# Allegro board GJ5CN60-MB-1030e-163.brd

Outline 196.2 x 189.15 mm; copper layers: TOP, L2_GND1, L3_IN1, L4_VCC1, L5_VCC2, L6_IN2, L7_GND2, L8_IN3, L9_GND3, BOTTOM. Coordinates in mm from the lower left corner of the outline.

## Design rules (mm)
net group 0_CAP: nets CAP+ CAP-
net group 0_SPKL1: nets SPKL1+ SPKL1-
net group 0_SPKR1: nets SPKR1+ SPKR1-
net group 20: nets USB_PN9 USB_PP9
net group AUX_EDP_CH_N: nets AUX_EDP_CH_N EDP_AUXN
net group AUX_EDP_CH_P: nets AUX_EDP_CH_P EDP_AUXP
net group CLK_24MHZ: nets PCH_XATL24_IN PCH_XTAL24_OUT
net group CNV_WR_CLK: nets CNV_WR_CLKN CNV_WR_CLKP
net group CNV_WR_D0: nets CNV_WR_D0N CNV_WR_D0P
net group CNV_WR_D1: nets CNV_WR_D1N CNV_WR_D1P
net group DIFFPAIR529: nets JACK_HP_L JACK_HP_R
net group DIFFPAIR531: nets HP_L HP_R
net group DIFFPAIR545: nets GPU_NVVDDS_FBRTN GPU_NVVDDS_SENSE
net group DIFFPAIR552: nets I2CC_SCL_G I2CC_SDA_G
net group DIFFPAIR553: nets I2CC_SCL I2CC_SDA
net group DIFFPAIR566: nets PCIE10_TXN PCIE10_TXP
net group DIFFPAIR567: nets PCIE11_TXN PCIE11_TXP
net group DIFFPAIR569: nets PCIE9_RXN PCIE9_RXP
net group DIFFPAIR587: nets I2CB_SCL_G I2CB_SDA_G
net group DIFFPAIR649: nets LINE2_L LINE2_R
net group DIFFPAIR669: nets E-USB-N2 E-USB-P2
net group DIFFPAIR723: nets PCIE20_RXN PCIE20_RXP
net group DIFFPAIR724: nets PCIE18_RXN PCIE18_RXP
net group DIFFPAIR725: nets PCIE19_RXN PCIE19_RXP
net group DIFFPAIR726: nets PCIE17_RXN PCIE17_RXP
net group DIFFPAIR727: nets CLK_CPU_BCLK_DN CLK_CPU_BCLK_DP
net group DIFFPAIR728: nets CLK_CPU_24MHZ_DN CLK_CPU_24MHZ_DP
net group DIFFPAIR729: nets CLK_CPU_PCIBCLK_DN CLK_CPU_PCIBCLK_DP
net group DIFFPAIR736: nets CLK_PCIE_WLAN_DN CLK_PCIE_WLAN_DP
net group DIFFPAIR746: nets N27873712 N27873827
net group DP9: nets IFPE_AUX_CK IFPE_AUX_DATA
net group DP_D0+: nets DP_D0+ EDP_TXP0
net group DP_D0-: nets DP_D0- EDP_TXN0
net group DP_D1+: nets DP_D1+ EDP_TXP1
net group DP_D1-: nets DP_D1- EDP_TXN1
net group DP_D2+: nets DP_D2+ EDP_TXP2
net group DP_D2-: nets DP_D2- EDP_TXN2
net group DP_D3+: nets DP_D3+ EDP_TXP3
net group DP_D3-: nets DP_D3- EDP_TXN3
net group I_VIN_N: nets I_VIN_N VIN1N_INA
net group TEMP_MPS: nets TEMP_MPS VRA_VTEMP
net group UART: nets UART2_DEBUG_RXD UART2_DEBUG_TXD
net group USB_PN2: nets N27867078 USB_PN2
net group USB_PP2: nets N27867098 USB_PP2
net group VCORE_VSSSENSE: nets VCORE_VSSSENSE VRACPU_VORTN
net group VRACPU_VDIFF: nets VRACPU_VDIFF VRACPU_VFB
net group VRAGT_VORTN: nets VRAGT_VORTN VSSGT_SENSE
net group 50_OHM: nets PLT_RST# SMBCLK_EC SMBDAT_EC
net group 85_OHM: nets E-USB-N1 E-USB-P1 PCIE_DETECT_SSD1
net group AUDIO: nets ACZ_BITCLK ACZ_BITCLK_PCH ACZ_RST# ACZ_RST#_PCH ACZ_SDATAIN0 ACZ_SDATAOUT ACZ_SDOUT_PCH ACZ_SYNC ACZ_SYNC_PCH
net group BAT: nets ACZ_SPKR_B1 ACZ_SPKR_B2 BAT_SMBCLK BAT_SMBDAT
net group BT/WIFI: nets CNV_BRI_DT CNV_BRI_RSP CNV_RGI_DT CNV_RGI_RSP
net group CLK_SRC: nets CLK_EC_LPC CLK_LAN_REQ CLK_TPM GFX_CLKREQ LAN_XTAL_IN LAN_XTAL_OUT MINI_CLKREQ0# MODEM_CLKREQ
net group CLS_DDR4_A_D0: nets M_A_DQ0 M_A_DQ1 M_A_DQ2 M_A_DQ3 M_A_DQ4 M_A_DQ5 M_A_DQ6 M_A_DQ7 M_B_DQ0 M_B_DQ1 M_B_DQ2 M_B_DQ3 M_B_DQ4 M_B_DQ5 M_B_DQ6 M_B_DQ7
net group CLS_DDR4_A_D1: nets M_A_DQ8 M_A_DQ9 M_A_DQ10 M_A_DQ11 M_A_DQ12 M_A_DQ13 M_A_DQ14 M_A_DQ15 M_B_DQ8 M_B_DQ9 M_B_DQ10 M_B_DQ11 M_B_DQ12 M_B_DQ13 M_B_DQ14 M_B_DQ15
net group CLS_DDR4_A_D2: nets M_A_DQ16 M_A_DQ17 M_A_DQ18 M_A_DQ19 M_A_DQ20 M_A_DQ21 M_A_DQ22 M_A_DQ23 M_B_DQ16 M_B_DQ17 M_B_DQ18 M_B_DQ19 M_B_DQ20 M_B_DQ21 M_B_DQ22 M_B_DQ23
net group CLS_DDR4_A_D3: nets M_A_DQ24 M_A_DQ25 M_A_DQ26 M_A_DQ27 M_A_DQ28 M_A_DQ29 M_A_DQ30 M_A_DQ31 M_B_DQ24 M_B_DQ25 M_B_DQ26 M_B_DQ27 M_B_DQ28 M_B_DQ29 M_B_DQ30 M_B_DQ31
net group CLS_DDR4_A_D4: nets M_A_DQ32 M_A_DQ33 M_A_DQ34 M_A_DQ35 M_A_DQ36 M_A_DQ37 M_A_DQ38 M_A_DQ39 M_B_DQ32 M_B_DQ33 M_B_DQ34 M_B_DQ35 M_B_DQ36 M_B_DQ37 M_B_DQ38 M_B_DQ39
net group CLS_DDR4_A_D5: nets M_A_DQ40 M_A_DQ41 M_A_DQ42 M_A_DQ43 M_A_DQ44 M_A_DQ45 M_A_DQ46 M_A_DQ47 M_B_DQ40 M_B_DQ41 M_B_DQ42 M_B_DQ43 M_B_DQ44 M_B_DQ45 M_B_DQ46 M_B_DQ47
net group CLS_DDR4_A_D6: nets M_A_DQ48 M_A_DQ49 M_A_DQ50 M_A_DQ51 M_A_DQ52 M_A_DQ53 M_A_DQ54 M_A_DQ55 M_B_DQ48 M_B_DQ49 M_B_DQ50 M_B_DQ51 M_B_DQ52 M_B_DQ53 M_B_DQ54 M_B_DQ55
net group CLS_DDR4_A_D7: nets M_A_DQ56 M_A_DQ57 M_A_DQ58 M_A_DQ59 M_A_DQ60 M_A_DQ61 M_A_DQ62 M_A_DQ63 M_B_DQ56 M_B_DQ57 M_B_DQ58 M_B_DQ59 M_B_DQ60 M_B_DQ61 M_B_DQ62 M_B_DQ63
net group CLS_DMI: nets DMI_RXN0 DMI_RXN1 DMI_RXN2 DMI_RXN3 DMI_RXP0 DMI_RXP1 DMI_RXP2 DMI_RXP3 DMI_TXN0 DMI_TXN1 DMI_TXN2 DMI_TXN3 DMI_TXP0 DMI_TXP1 DMI_TXP2 DMI_TXP3
net group CLS_FB_A_CLK: nets FBA_CLK0_N FBA_CLK0_P FBA_CLK1_N FBA_CLK1_P
net group CLS_FB_A_CMD: nets FBA_CMD0 FBA_CMD1 FBA_CMD2 FBA_CMD3 FBA_CMD4 FBA_CMD5 FBA_CMD6 FBA_CMD7 FBA_CMD8 FBA_CMD9 FBA_CMD10 FBA_CMD11 FBA_CMD12 FBA_CMD13 FBA_CMD14 FBA_CMD15
net group CLS_FB_A_CMD1: nets FBA_CMD16 FBA_CMD17 FBA_CMD18 FBA_CMD19 FBA_CMD20 FBA_CMD21 FBA_CMD22 FBA_CMD23 FBA_CMD24 FBA_CMD25 FBA_CMD26 FBA_CMD27 FBA_CMD28 FBA_CMD29 FBA_CMD30 FBA_CMD31
net group CLS_FB_A_WCK: nets FBA_WCK01_N FBA_WCK01_P FBA_WCK23_N FBA_WCK23_P FBA_WCK45_N FBA_WCK45_P FBA_WCK67_N FBA_WCK67_P
net group CLS_FB_B_CLK: nets FBB_CLK0_N FBB_CLK0_P FBB_CLK1_N FBB_CLK1_P
net group CLS_FB_B_CMD: nets FBB_CMD0 FBB_CMD1 FBB_CMD2 FBB_CMD3 FBB_CMD4 FBB_CMD5 FBB_CMD6 FBB_CMD7 FBB_CMD8 FBB_CMD9 FBB_CMD10 FBB_CMD11 FBB_CMD12 FBB_CMD13 FBB_CMD14 FBB_CMD15
net group CLS_FB_B_CMD1: nets FBB_CMD16 FBB_CMD17 FBB_CMD18 FBB_CMD19 FBB_CMD20 FBB_CMD21 FBB_CMD22 FBB_CMD23 FBB_CMD24 FBB_CMD25 FBB_CMD26 FBB_CMD27 FBB_CMD28 FBB_CMD29 FBB_CMD30 FBB_CMD31
net group CLS_FB_B_WCK: nets FBB_WCK01_N FBB_WCK01_P FBB_WCK23_N FBB_WCK23_P FBB_WCK45_N FBB_WCK45_P FBB_WCK67_N FBB_WCK67_P
net group CLS_FB_C_CLK: nets FBC_CLK0_N FBC_CLK0_P FBC_CLK1_N FBC_CLK1_P
net group CLS_FB_C_CMD: nets FBC_CMD0 FBC_CMD1 FBC_CMD2 FBC_CMD3 FBC_CMD4 FBC_CMD5 FBC_CMD6 FBC_CMD7 FBC_CMD8 FBC_CMD9 FBC_CMD10 FBC_CMD11 FBC_CMD12 FBC_CMD13 FBC_CMD14 FBC_CMD15
net group CLS_FB_C_CMD1: nets FBC_CMD16 FBC_CMD17 FBC_CMD18 FBC_CMD19 FBC_CMD20 FBC_CMD21 FBC_CMD22 FBC_CMD23 FBC_CMD24 FBC_CMD25 FBC_CMD26 FBC_CMD27 FBC_CMD28 FBC_CMD29 FBC_CMD30 FBC_CMD31
net group CLS_FB_C_WCK: nets FBC_WCK01_N FBC_WCK01_P FBC_WCK23_N FBC_WCK23_P FBC_WCK45_N FBC_WCK45_P FBC_WCK67_N FBC_WCK67_P
net group CLS_LAN_TR: nets TR0+ TR0- TR1+ TR1- TR2+ TR2- TR3+ TR3-
net group CLS_LN_MDI: nets LAN_MDI0+ LAN_MDI0- LAN_MDI1+ LAN_MDI1- LAN_MDI2+ LAN_MDI2-
net group CLS_LPC: nets LPC_AD0 LPC_AD1 LPC_AD2 LPC_AD3 LPC_FRAME#
net group CLS_PCIE_CLK: nets CLK_PCIE_GFX_DN CLK_PCIE_GFX_DP CLK_PCIE_LAN_DN CLK_PCIE_LAN_DP PCIE4_CLKN_MD2_SSD1 PCIE4_CLKP_MD2_SSD1 PCIE6_CLKN_MD2_SSD2 PCIE6_CLKP_MD2_SSD2
net group CLS_PCIE_P: nets DGPU_PEX_RXN_0 DGPU_PEX_RXN_1 DGPU_PEX_RXN_2 DGPU_PEX_RXN_3 DGPU_PEX_RXN_4 DGPU_PEX_RXN_5 DGPU_PEX_RXN_6 DGPU_PEX_RXN_7 DGPU_PEX_RXN_8 DGPU_PEX_RXN_9 DGPU_PEX_RXN_10 DGPU_PEX_RXN_11 DGPU_PEX_RXN_12 DGPU_PEX_RXN_13 DGPU_PEX_RXN_14 DGPU_PEX_RXN_15 DGPU_PEX_RXP_0 DGPU_PEX_RXP_1 DGPU_PEX_RXP_2 DGPU_PEX_RXP_3 DGPU_PEX_RXP_4 DGPU_PEX_RXP_5 DGPU_PEX_RXP_6 DGPU_PEX_RXP_7 DGPU_PEX_RXP_8 DGPU_PEX_RXP_9 DGPU_PEX_RXP_10 DGPU_PEX_RXP_11 DGPU_PEX_RXP_12 DGPU_PEX_RXP_13 DGPU_PEX_RXP_14 DGPU_PEX_RXP_15 DGPU_PEX_TXN_0 DGPU_PEX_TXN_1 DGPU_PEX_TXN_2 DGPU_PEX_TXN_3 DGPU_PEX_TXN_4 DGPU_PEX_TXN_5 DGPU_PEX_TXN_6 DGPU_PEX_TXN_7 DGPU_PEX_TXN_8 DGPU_PEX_TXN_9 DGPU_PEX_TXN_10 DGPU_PEX_TXN_11 DGPU_PEX_TXN_12 DGPU_PEX_TXN_13 DGPU_PEX_TXN_14 DGPU_PEX_TXN_15 DGPU_PEX_TXP_1 DGPU_PEX_TXP_3 DGPU_PEX_TXP_5 DGPU_PEX_TXP_7 DGPU_PEX_TXP_9 DGPU_PEX_TXP_11 DGPU_PEX_TXP_13 DGPU_PEX_TXP_15 PEG_TXN0 PEG_TXN1 PEG_TXN2 PEG_TXN3 PEG_TXN4 PEG_TXN5 PEG_TXN6 PEG_TXN7 PEG_TXN8 PEG_TXN9 PEG_TXN10 PEG_TXN11 PEG_TXN12 PEG_TXN13 PEG_TXN14 PEG_TXN15 PEG_TXP0 PEG_TXP1 PEG_TXP2 PEG_TXP3 PEG_TXP4 PEG_TXP5 PEG_TXP6 PEG_TXP7 PEG_TXP8 PEG_TXP9 PEG_TXP10 PEG_TXP11 PEG_TXP12 PEG_TXP13 PEG_TXP14 PEG_TXP15 PEX_RXN0 PEX_RXN1 PEX_RXN2 PEX_RXN3 PEX_RXN4 PEX_RXN5 PEX_RXN6 PEX_RXN7 PEX_RXN8 PEX_RXN9 PEX_RXN10 PEX_RXN11 PEX_RXN12 PEX_RXN13 PEX_RXN14 PEX_RXN15 PEX_RXP0 PEX_RXP1 PEX_RXP2 PEX_RXP3 PEX_RXP4 PEX_RXP5 PEX_RXP6 PEX_RXP7 PEX_RXP8 PEX_RXP9 PEX_RXP10 PEX_RXP11 PEX_RXP12 PEX_RXP13 PEX_RXP14 PEX_RXP15
net group CLS_SATA: nets SATA_RXN0 SATA_RXN0_C SATA_RXP0 SATA_RXP0_C SATA_TXN0 SATA_TXN0_C SATA_TXP0 SATA_TXP0_C
net group CLS_USB3: nets USB3_TX1_N_C USB3_TX1_P_C USB3_TX3_N_C USB3_TX3_P_C USB3_TX5_N_C USB3_TX5_P_C USB3_TX6_N_C USB3_TX6_P_C USB31_5_RX_N USB31_5_RX_P USB31_5_TX_N USB31_5_TX_P USB31_6_RX_N USB31_6_RX_P USB31_6_TX_N USB31_6_TX_P USB32_RX_N_IN USB32_RX_P_IN USB32_TX_N_IN USB32_TX_P_IN USB33_RX_N_IN USB33_RX_P_IN USB33_TX_N_IN USB33_TX_P_IN
net group CNVIO: nets CNV_WT_CLKN CNV_WT_CLKP CNV_WT_D0N CNV_WT_D0P CNV_WT_D1N CNV_WT_D1P
net group DDR4_A_CMD: nets DDR0_A_ALERT_N DDR0_A_PARITY M_A_A0 M_A_A1 M_A_A2 M_A_A3 M_A_A4 M_A_A5 M_A_A6 M_A_A7 M_A_A8 M_A_A9 M_A_A10_AP M_A_A11 M_A_A12 M_A_A13 M_A_A14_MA_WE# M_A_A15_MA_CAS# M_A_A16_MA_RAS# M_A_ACT_N M_A_BA0 M_A_BA1 M_A_BG0 M_A_BG1
net group DDR4_A_CTRL: nets MA_CKE0 MA_CKE1 MA_CS#0 MA_CS#1 MA_ODT0 MA_ODT1
net group DDR4_B_CMD: nets DDR1_B_ALERT_N DDR1_B_PARITY M_B_A0 M_B_A1 M_B_A2 M_B_A3 M_B_A4 M_B_A5 M_B_A6 M_B_A7 M_B_A8 M_B_A9 M_B_A10_AP M_B_A11 M_B_A12 M_B_A13 M_B_A14_MB_WE# M_B_A15_MB_CAS# M_B_A16_MB_RAS# M_B_ACT_N M_B_BA0 M_B_BA1 M_B_BG0 M_B_BG1
net group DDR4_B_CTRL: nets MB_CKE0 MB_CKE1 MB_CS#0 MB_CS#1 MB_ODT0 MB_ODT1
net group DDR4_CLK: nets MA_CLK0 MA_CLK1 MA_CLK#0 MA_CLK#1 MB_CLK1 MB_CLK#1
net group DDR4_DQS: nets M_A_DQS3 M_A_DQS5 M_A_DQS#3 M_A_DQS#5 M_B_DQS0 M_B_DQS1 M_B_DQS2 M_B_DQS3 M_B_DQS4 M_B_DQS5 M_B_DQS6 M_B_DQS#0 M_B_DQS#1 M_B_DQS#2 M_B_DQS#3 M_B_DQS#4 M_B_DQS#5 M_B_DQS#6
net group DIFFPAIR570: nets PCIE9_TXN
net group FB_A_D0: nets FBA_D0 FBA_D1 FBA_D2 FBA_D3 FBA_D4 FBA_D5 FBA_D6 FBA_D7 FBA_DBI0 FBA_EDC0
net group FB_A_D1: nets FBA_D8 FBA_D9 FBA_D10 FBA_D11 FBA_D12 FBA_D13 FBA_D14 FBA_D15 FBA_DBI1 FBA_EDC1
net group FB_A_D2: nets FBA_D16 FBA_D17 FBA_D18 FBA_D19 FBA_D20 FBA_D21 FBA_D22 FBA_D23 FBA_DBI2 FBA_EDC2
net group FB_A_D3: nets FBA_D24 FBA_D25 FBA_D26 FBA_D27 FBA_D28 FBA_D29 FBA_D30 FBA_D31 FBA_DBI3 FBA_EDC3
net group FB_A_D4: nets FBA_D32 FBA_D33 FBA_D34 FBA_D35 FBA_D36 FBA_D37 FBA_D38 FBA_D39 FBA_DBI4 FBA_EDC4
net group FB_A_D5: nets FBA_D40 FBA_D41 FBA_D42 FBA_D43 FBA_D44 FBA_D45 FBA_D46 FBA_D47 FBA_DBI5 FBA_EDC5
net group FB_A_D6: nets FBA_D48 FBA_D49 FBA_D50 FBA_D51 FBA_D52 FBA_D53 FBA_D54 FBA_D55 FBA_DBI6 FBA_EDC6
net group FB_A_D7: nets FBA_D56 FBA_D57 FBA_D58 FBA_D59 FBA_D60 FBA_D61 FBA_D62 FBA_D63 FBA_DBI7 FBA_EDC7
net group FB_B_D_0: nets FBB_D0 FBB_D1 FBB_D2 FBB_D3 FBB_D4 FBB_D5 FBB_D6 FBB_D7 FBB_DBI0 FBB_EDC0
net group FB_B_D_1: nets FBB_D8 FBB_D9 FBB_D10 FBB_D11 FBB_D12 FBB_D13 FBB_D14 FBB_D15 FBB_DBI1 FBB_EDC1
net group FB_B_D_2: nets FBB_D16 FBB_D17 FBB_D18 FBB_D19 FBB_D20 FBB_D21 FBB_D22 FBB_D23 FBB_DBI2 FBB_EDC2
net group FB_B_D_3: nets FBB_D24 FBB_D25 FBB_D26 FBB_D27 FBB_D28 FBB_D29 FBB_D30 FBB_D31 FBB_DBI3 FBB_EDC3
net group FB_B_D_4: nets FBB_D32 FBB_D33 FBB_D34 FBB_D35 FBB_D36 FBB_D37 FBB_D38 FBB_D39 FBB_DBI4 FBB_EDC4
net group FB_B_D_5: nets FBB_D40 FBB_D41 FBB_D42 FBB_D43 FBB_D44 FBB_D45 FBB_D46 FBB_D47 FBB_DBI5 FBB_EDC5
net group FB_B_D_6: nets FBB_D48 FBB_D49 FBB_D50 FBB_D51 FBB_D52 FBB_D53 FBB_D54 FBB_D55 FBB_DBI6 FBB_EDC6
net group FB_B_D_7: nets FBB_D56 FBB_D57 FBB_D58 FBB_D59 FBB_D60 FBB_D61 FBB_D62 FBB_D63 FBB_DBI7 FBB_EDC7
net group FB_C_D_0: nets FBC_D0 FBC_D1 FBC_D2 FBC_D3 FBC_D4 FBC_D5 FBC_D6 FBC_D7 FBC_DBI0 FBC_EDC0
net group FB_C_D_1: nets FBC_D8 FBC_D9 FBC_D10 FBC_D11 FBC_D12 FBC_D13 FBC_D14 FBC_D15 FBC_DBI1 FBC_EDC1
net group FB_C_D_2: nets FBC_D16 FBC_D17 FBC_D18 FBC_D19 FBC_D20 FBC_D21 FBC_D22 FBC_D23 FBC_DBI2 FBC_EDC2
net group FB_C_D_3: nets FBC_D24 FBC_D25 FBC_D26 FBC_D27 FBC_D28 FBC_D29 FBC_D30 FBC_D31 FBC_DBI3 FBC_EDC3
net group FB_C_D_4: nets FBC_D32 FBC_D33 FBC_D34 FBC_D35 FBC_D36 FBC_D37 FBC_D38 FBC_D39 FBC_DBI4 FBC_EDC4
net group FB_C_D_5: nets FBC_D40 FBC_D41 FBC_D42 FBC_D43 FBC_D44 FBC_D45 FBC_D46 FBC_D47 FBC_DBI5 FBC_EDC5
net group FB_C_D_6: nets FBC_D48 FBC_D49 FBC_D50 FBC_D51 FBC_D52 FBC_D53 FBC_D54 FBC_D55 FBC_DBI6 FBC_EDC6
net group FB_C_D_7: nets FBC_D56 FBC_D57 FBC_D58 FBC_D59 FBC_D60 FBC_D61 FBC_D62 FBC_D63 FBC_DBI7 FBC_EDC7
net group HDMIOUT_CLK+: nets HDMI1_CLK_DP HDMIOUT_CLK+ N24336873 TMDSB_CLK+
net group HDMIOUT_CLK-: nets HDMI1_CLK_DN HDMIOUT_CLK- N24336854 TMDSB_CLK-
net group HDMIOUT_D0+: nets HDMI1_TX0_DP HDMIOUT_D0+ N24336578 TMDSB_D0+
net group HDMIOUT_D0-: nets HDMI1_TX0_DN HDMIOUT_D0- N24336526 TMDSB_D0-
net group HDMIOUT_D1+: nets HDMI1_TX1_DP HDMIOUT_D1+ N24336705 TMDSB_D1+
net group HDMIOUT_D1-: nets HDMI1_TX1_DN HDMIOUT_D1- N24336650 TMDSB_D1-
net group HDMIOUT_D2+: nets HDMI1_TX2_DP HDMIOUT_D2+ N24336771 TMDSB_D2+
net group HDMIOUT_D2-: nets HDMI1_TX2_DN HDMIOUT_D2- N24336752 TMDSB_D2-
net group PCH_SPI: nets PCH_SPI0_IO2 PCH_SPI0_IO3 PCH_SPI_CLK PCH_SPI_CS0# PCH_SPI_HOLD# PCH_SPI_SI PCH_SPI_SI_R PCH_SPI_SO PCH_SPI_SO_R PCH_SPI_WP PCH_XCLK_BIASREF
net group PCIE: nets N28935332 N28935334 PCIE9_TXN_C PCIE9_TXP PCIE9_TXP_C PCIE10_RXN PCIE10_RXP PCIE10_TXN_C PCIE10_TXP_C PCIE11_RXN PCIE11_RXP PCIE11_TXN_C PCIE11_TXP_C PCIE12_RXN PCIE12_RXP PCIE12_TXN PCIE12_TXN_C PCIE12_TXP PCIE12_TXP_C PCIE14_RXN PCIE14_RXP PCIE14_TXN PCIE14_TXP PCIE15_RXN PCIE15_RXP PCIE15_TXN PCIE15_TXP PCIE17_TXN PCIE17_TXN_C PCIE17_TXP PCIE17_TXP_C PCIE18_TXN PCIE18_TXN_C PCIE18_TXP PCIE18_TXP_C PCIE19_TXN PCIE19_TXN_C PCIE19_TXP PCIE19_TXP_C PCIE20_TXN PCIE20_TXN_C PCIE20_TXP PCIE20_TXP_C PCIE_TXN14_C PCIE_TXP14_C
net group PEX_RXP1: nets DGPU_PEX_TXP_14
net group PEX_RXP3: nets DGPU_PEX_TXP_12
net group PEX_RXP5: nets DGPU_PEX_TXP_10
net group PEX_RXP7: nets DGPU_PEX_TXP_8
net group PEX_RXP9: nets DGPU_PEX_TXP_6
net group PEX_RXP11: nets DGPU_PEX_TXP_4
net group PEX_RXP13: nets DGPU_PEX_TXP_2
net group PEX_RXP15: nets DGPU_PEX_TXP_0
net group RTC: nets RTC_X1 RTC_X2 RTCRST# SRTCRST#
net group SIDEHAND: nets CATERR# EC_PECI H_THERMTRIP_N PCH_2_CPU_TRIGGER PCH_PCIE_WAKE# PCH_PLTRST_PROC PCH_PM_SYNC PCH_PWROK PM_DOWN PM_DOWN_R PM_SYNC PROCHOT# PROCHOT#_R PROCHOT_# PROCPWRGD_CPU VCCST_PWRGD VCCST_PWRGD_R VCCST_PWRON_R VR_VIDALERT# VR_VIDSCK VR_VIDSOUT
net group SPI: nets SPI_CE# SPI_SI SPI_SO
net group USB2.0: nets TYPE_C_D1+ TYPE_C_D1- TYPE_C_D2+ TYPE_C_D2- USB_PN1 USB_PN3 USB_PN4 USB_PN5 USB_PN6 USB_PN7 USB_PN8 USB_PN12 USB_PN13 USB_PN14 USB_PP1 USB_PP3 USB_PP4 USB_PP5 USB_PP6 USB_PP7 USB_PP8 USB_PP12 USB_PP13 USB_PP14
net group USB3: nets TYPC_RX1+ TYPC_RX1- TYPC_RX2+ TYPC_RX2- TYPC_TX1+ TYPC_TX1- TYPC_TX2+ TYPC_TX2- USB31_1_RX_N USB31_1_RX_P USB31_1_TX_N USB31_1_TX_P USB31_3_RX_N USB31_3_RX_P USB31_3_TX_N USB31_3_TX_P
nets with their own width: min track width 0.114; nets EDP_HPD
nets with their own width: min track width 0.254; nets +3.3VA_RTC JACK_MIC1_R MIC1_VREF_L MIC1_VREF_R
nets with their own width: min track width 0.381; nets DC_IN DC_IN+ DC_IN_B GND POWER
nets with their own width: min track width 0.508; nets 1V8_AON 1V8_MAIN +0.6V_DDR +1.00V_CPU +1.0VA_PCH +1.00VS_CPU +1.2VS +2.5VS +3.3V +3.3VA +3.3VDVDD +3.3VS +5V +5V_3.3V_L +5V_AMP +5VA +5VS +V_DDR_VREFCA_CHB_DIMM +VCCCORE +VCCDSW_3P3 +VCCGT +VCCIO +VCCSA BAT+ CHG_LX CODEC_GND EC_3.3VA FAN_SPEED FAN_SPEED1 FBCAL_GND FBVDDQ_MEM GND_BQ24781S HDMI_5V_C HDMI_+5V M_VREF_CA_DIMM0 NVVDDS PEX_VDD PWR_B_LED_GND PWR_LED+ S_GND_R V_DDR_CA_VREF VIN VIN_LCD VIN_LCD_IN0 WEBCAM_+5V
nets with their own width: min track width 0.635; nets G_HDR1_R G_LDR1 G_LDR2 PHASE_GCORE1

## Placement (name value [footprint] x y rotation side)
AB1  -  [M-R0402]  21.67 56.85 180 bottom
AB2  -  [M-R0603]  32.08 55.71 0 top
AB3  -  [M-R0402]  22.3 62.18 90 bottom
AB4  -  [M-R0402]  20.67 65.13 0 top
AB5  -  [M-R0402]  13.54 55.58 0 top
AB6  -  [M-R0603]  28.52 55.2 0 top
AB8  -  [M-B0603]  67.51 48.09 270 bottom
AB9  -  [M-B0603]  68.91 48.09 270 bottom
AB11  -  [M-B0603]  70.31 48.09 270 bottom
AB12  -  [M-B0603]  71.7 48.09 270 bottom
AC3  -  [M-C0402]  20.27 55.32 180 top
AC4  -  [M-C0603]  26.36 54.44 270 top
AC5  -  [M-C0402]  22.3 54.18 270 top
AC6  -  [M-C0402]  15.65 63.32 270 top
AC7  -  [M-C0402]  14.63 63.32 270 top
AC8  -  [M-C0603]  23.44 54.05 270 top
AC9  -  [M-C0402]  25.17 54.08 270 top
ACN1  VALUE*  [CON_WB-4H125_11255W90-NP_JCTC]  78.73 39.74 180 bottom
AR5  -  [M-R0402]  26.38 64.85 90 top
AR6  -  [M-R0402]  22.02 64.85 90 top
AR8  -  [M-R0402]  14.63 60.52 90 top
AR9  -  [M-R0402]  15.65 60.52 90 top
AR11  -  [M-R0402]  16.2 57.23 0 top
AR12  -  [M-R0402]  16.2 58.25 0 top
AR13  -  [M-R0402]  17.86 59.01 0 top
AR14  -  [M-R0402]  18.24 60.15 0 top
AR17  -  [M-R0402]  25.22 64.85 90 top
AR18  -  [M-R0402]  15.14 61.92 180 top
AR25  -  [M-R0603]  17.73 55.32 180 top
B1  -  [M-R0603]  163.78 15.57 180 top
B2  -  [M-B0402]  147.4 28.65 180 top
B7  -  [M-B0603]  79.07 159.85 90 top
B10  -  [M-B0603]  59.26 159.97 0 top
B12  -  [M-B0603]  59.26 161.37 0 top
B13  VALUE*  [M-B0805]  39.06 168.35 270 top
B14  -  [FUSE-0805]  77.29 159.21 90 top
B15  -  [M-B0402]  71.7 156.8 180 bottom
B16  -  [M-B0402]  71.7 155.53 180 bottom
B19  -  [M-B0603]  60.53 174.58 270 top
B20  VALUE*  [M-B0805]  36.78 168.35 270 top
B25  -  [FUSE-0805]  81.36 157.69 0 top
B26  -  [M-R0805]  71.2 159.97 90 top
B27  -  [M-R0402]  80.72 77.04 180 top
B34  -  [M-R0402]  82.63 77.04 0 top
B36  VALUE*  [M-B0805]  27 40.21 180 top
B37  VALUE*  [M-B0805]  27 44.02 180 top
C2  -  [M-C0402]  189.31 135.84 90 top
C3  -  [M-C0603]  117.42 145.24 90 bottom
C4  -  [M-C0402]  176.48 162.13 270 top
C5  -  [M-C0603]  139.14 114.38 180 bottom
C6  -  [M-C0603]  144.47 114.38 180 bottom
C7  -  [M-C0603]  147.01 123.4 0 bottom
C8  -  [M-C0402]  15.7 154.13 180 bottom
C9  -  [M-C0603]  139.14 112.98 180 bottom
C10  -  [M-C0603]  133.93 117.55 180 bottom
C11  -  [M-C0603]  133.81 121.75 180 bottom
C13  -  [M-C0402]  182.7 165.31 270 top
C14  -  [M-C0402]  171.53 158.83 90 top
C15  -  [M-C0402]  175.59 162.13 270 top
C16  -  [M-C0402]  184.48 86.57 180 bottom
C17  -  [M-C0402]  184.48 85.68 180 bottom
C18  -  [M-C0402]  184.48 84.79 180 bottom
C19  -  [M-C0402]  184.48 83.9 180 bottom
C21  -  [M-C0402]  183.72 81.99 0 bottom
C22  -  [M-C0603]  133.81 123.14 180 bottom
C23  -  [M-C0603]  183.46 79.84 180 bottom
C24  -  [M-C0603]  139.14 122 180 bottom
C25  -  [M-C0603]  141.81 113.02 0 bottom
C26  -  [M-C0603]  128.55 137.57 180 top
C27  -  [M-C0603]  128.52 134.78 180 top
C28  -  [M-C0603]  147.22 141.38 0 bottom
C29  -  [M-C0603]  147.29 135.36 0 top
C30  -  [M-C0603]  147.29 136.76 0 top
C31  -  [M-C0603]  114.12 144.22 180 top
C32  -  [M-C0603]  147.29 138.15 0 top
C33  -  [M-C0603]  139.14 123.4 180 bottom
C34  -  [M-C0603]  128.55 136.17 180 top
C35  -  [M-C0603]  141.81 114.42 0 bottom
C36  -  [M-C0603]  136.47 122 0 bottom
C37  -  [M-C0603]  114.12 140.03 180 top
C38  -  [M-C0603]  114.12 141.43 180 top
C39  -  [M-C0603]  114.12 147.02 180 top
C40  -  [M-C0603]  133.93 116.16 180 bottom
C41  -  [M-C0603]  133.93 114.76 180 bottom
C42  -  [M-C0402]  131.01 131.52 270 bottom
C43  -  [M-C0603]  136.47 112.98 0 bottom
C44  -  [M-C0402]  146.51 111.59 0 bottom
C45  -  [M-C0402]  144.47 111.59 180 bottom
C46  -  [M-C0402]  143.2 5.79 270 top
C47  -  [M-C0402]  131.27 114 90 bottom
C48  -  [M-C0402]  133.93 111.59 0 bottom
C49  -  [M-C0402]  134.95 128.86 270 bottom
C50  -  [M-C0402]  134.95 131.4 270 bottom
C51  -  [M-C0603]  114.12 145.62 180 top
C52  -  [M-C0402]  139.7 131.78 0 bottom
C53  -  [M-C0402]  135.08 126.44 270 bottom
C54  -  [M-C0402]  141.3 128.1 90 bottom
C55  -  [M-C0603]  144.47 112.98 180 bottom
C56  -  [M-C0402]  141.02 125.38 270 bottom
C57  -  [M-C0402]  132.54 131.4 270 bottom
C58  -  [M-C0402]  141.55 129.64 0 bottom
C59  -  [M-C0402]  144.35 126.7 90 bottom
C60  -  [M-C0402]  145.64 126.98 0 bottom
C61  -  [M-C0402]  144.35 129.24 90 bottom
C62  -  [M-C0402]  132.16 114 90 bottom
C63  -  [M-C0402]  143.71 131.02 90 bottom
C64  -  [M-C0402]  138.89 126.83 270 bottom
C65  -  [M-C0402]  137.24 132.03 270 bottom
C66  -  [M-C0402]  132.54 128.98 270 bottom
C67  -  [M-C0603]  147.01 122 0 bottom
C68  -  [M-C0402]  182.32 17.05 0 top
C69  -  [M-C0402]  143.13 125.23 0 bottom
C70  -  [M-C0603]  144.47 123.4 180 bottom
C71  -  [M-C0603]  141.81 123.4 0 bottom
C72  -  [M-C0402]  132.03 80.78 0 bottom
C73  -  [M-C0402]  136.09 81.23 90 bottom
C74  -  [M-C0402]  154.38 65.74 90 bottom
C75  -  [M-C0402]  138.12 130.64 270 bottom
C76  -  [M-C0402]  139.27 65.48 90 bottom
C77  -  [M-C0603]  139.39 132.92 0 bottom
C78  -  [M-C0402]  137.49 65.48 270 bottom
C79  -  [M-C0603]  146.38 124.92 0 bottom
C80  -  [M-C0402]  132.54 124.79 270 bottom
C81  -  [M-C0603]  133.93 113.36 180 bottom
C82  -  [M-C0402]  178.76 17.05 0 top
C83  -  [M-C0402]  91.13 44.15 270 top
C84  -  [M-C0402]  175.98 14.47 0 top
C85  -  [M-C0402]  89.25 47.07 270 top
C86  -  [M-C0402]  103.07 160.1 180 top
C87  -  [M-C0402]  176.48 16.97 0 top
C88  -  [M-C0402]  91.52 46.36 270 top
C89  -  [M-C0402]  102.95 162.77 270 top
C90  -  [M-C0603]  114.12 142.83 180 top
C91  -  [M-C0603]  144.47 122 180 bottom
C92  -  [M-C0603]  141.81 122 0 bottom
C93  -  [M-C0402]  155.85 127.08 180 bottom
C94  -  [M-C0402]  151.15 128.48 180 bottom
C95  -  [M-C0603]  151.97 124.67 0 bottom
C96  -  [M-C0402]  153.87 124.79 270 bottom
C97  -  [M-C0603]  151.97 123.27 0 bottom
C98  -  [M-C0603]  136.47 123.4 0 bottom
C99  -  [M-C0603]  152.86 114.38 0 bottom
C100  -  [M-C0402]  153.24 131.14 0 bottom
C101  -  [M-C0402]  160.48 114.89 0 bottom
C102  -  [M-C0603]  155.52 115.01 180 bottom
C103  -  [M-C0603]  133.93 118.95 180 bottom
C104  -  [M-C0603]  155.52 117.81 180 bottom
C105  -  [M-C0402]  159.97 116.54 0 bottom
C106  -  [M-C0603]  155.52 120.6 180 bottom
C107  -  [M-C0402]  159.82 121.97 0 bottom
C108  -  [M-C0603]  133.93 120.35 180 bottom
C109  -  [M-C0402]  160.48 114 0 bottom
C110  -  [M-C0603]  155.52 116.41 180 bottom
C111  -  [M-C0603]  155.52 119.21 180 bottom
C112  -  [M-C0603]  155.52 122 180 bottom
C113  -  [M-C0402]  190.45 104.98 0 top
C114  -  [M-C0402]  158.06 114 270 bottom
C115  -  [M-C0402]  154.15 111.59 180 bottom
C116  -  [M-C0603]  155.52 123.4 180 bottom
C117  -  [M-C0603]  152.86 112.98 0 bottom
C118  -  [M-C0402]  152.63 115.52 0 bottom
C119  -  [M-C0402]  186.13 111.71 0 bottom
C120  -  [M-C0402]  188.6 112.2 90 top
C121  -  [M-C0603]  148.03 114.38 180 bottom
C122  -  [M-C0603]  159.21 132.67 270 bottom
C123  -  [M-C0603]  149.55 123.27 0 bottom
C125  -  [M-C0603]  156.16 132.54 270 bottom
C126  -  [M-C0402]  160.22 14.68 270 top
C127  -  [M-C0603]  148.03 112.98 180 bottom
C128  -  [M-C0402]  59 55.96 270 top
C129  -  [M-C0402]  59.89 55.96 270 top
C130  -  [M-C0402]  29.41 65.1 180 top
C131  -  [M-C0402]  31.7 62.44 0 top
C132  -  [M-C0603]  155.52 113.62 180 bottom
C133  -  [M-C0402]  158.19 125.17 0 bottom
C134  -  [M-C0402]  65.53 59.01 180 top
C135  -  [M-C0603]  140.16 81.49 90 bottom
C136  -  [M-C0402]  29.41 61.55 180 top
C137  -  [M-C0402]  29.46 62.44 180 top
C138  -  [M-C0402]  31.7 63.33 0 top
C139  -  [M-C0402]  28.02 62.94 270 top
C140  -  [M-C0402]  24.33 64.85 90 top
C141  -  [M-C0402]  22.91 64.85 90 top
C142  -  [M-C0402]  144.22 25.35 180 bottom
C143  -  [M-C0603]  20.27 54.18 0 top
C144  -  [M-C0603]  169.87 141.81 90 bottom
C145  -  [M-C0402]  190.47 102.75 0 top
C146  -  [M-C0603]  131.14 116.92 0 bottom
C147  -  [M-C0402]  144.22 18.62 180 bottom
C148  -  [M-C0603]  171.14 134.95 0 top
C149  -  [M-C0603]  136.47 105.74 270 bottom
C150  -  [M-C0402]  130.89 123.98 0 bottom
C151  -  [M-C0402]  2.36 105.11 0 top
C152  -  [M-C0603]  171.09 137.67 0 top
C153  -  [M-C0603]  119.71 133.43 180 bottom
C154  -  [M-C0402]  187.88 102.95 90 top
C155  -  [M-C0402]  185.88 141.18 90 top
C156  -  [M-C0402]  186.89 141.18 90 top
C157  -  [M-C0402]  187.91 141.18 90 top
C158  -  [M-C0402]  182.7 139.14 0 top
C159  -  [M-C0603]  189.81 106.76 270 top
C160  -  [M-C0603]  191.29 106.76 270 top
C161  -  [M-C0402]  18.62 61.67 90 top
C162  -  [M-C0402]  165.81 21.42 0 bottom
C163  -  [M-C0402]  17.86 61.67 90 top
C164  -  [M-C0402]  29.41 59.64 180 top
C165  -  [M-C0402]  176.73 143.72 90 top
C166  -  [M-C0402]  176.73 145.49 270 top
C167  -  [M-C0603]  134.06 105.74 270 bottom
C168  -  [M-C0402]  165.81 22.3 0 bottom
C169  -  [M-C0603]  176.88 102.72 270 top
C170  -  [M-C0603]  175.46 102.72 270 top
C171  -  [M-C0603]  179.15 104.65 0 top
C172  -  [M-C0402]  29.92 58.75 180 top
C173  -  [M-C0603]  115.01 134.19 180 top
C174  -  [M-C0402]  191.59 134.45 0 top
C175  -  [M-C0402]  165.81 23.19 0 bottom
C176  -  [M-C0603]  143.59 68.41 90 bottom
C177  -  [M-C0402]  154.63 11.26 270 bottom
C178  -  [M-C0402]  18.03 56.86 270 top
C179  -  [M-C0402]  18.92 56.86 90 top
C180  -  [M-C0402]  31.82 58.32 0 top
C181  -  [M-C0603]  186.77 111.84 180 top
C182  -  [M-C0402]  144.22 17.73 180 bottom
C183  -  [M-C0402]  18.29 63.05 180 top
C184  -  [M-C0603]  150.06 105.87 270 bottom
C185  -  [M-C0603]  189.25 109.55 90 top
C186  -  [M-C0603]  131.27 119.74 0 bottom
C187  -  [M-C0603]  153.24 68.53 90 bottom
C188  -  [M-C0603]  122.25 127.84 180 bottom
C189  -  [M-C0603]  146.51 105.74 270 bottom
C190  -  [M-C0603]  178.31 102.72 270 top
C191  -  [M-C0603]  142.19 110.94 90 bottom
C192  -  [M-C0603]  171.14 143.21 0 top
C193  -  [M-C0603]  190.73 109.55 90 top
C194  -  [M-C0402]  14.81 56.85 270 top
C195  -  [M-C0402]  14.81 58.63 90 top
C196  -  [M-C0603]  143.59 105.74 270 bottom
C197  -  [M-C0603]  141.81 173.69 0 top
C198  -  [M-C0402]  121.87 170.39 180 bottom
C199  -  [M-C0603]  18.06 64.19 0 top
C200  -  [M-C0603]  141.81 173.69 0 bottom
C201  -  [M-C0603]  141.81 175.09 0 bottom
C202  -  [M-C0603]  141.81 175.09 0 top
C203  -  [M-C0402]  158.57 112.09 270 bottom
C204  -  [M-C0603]  121.74 132.16 180 bottom
C205  -  [M-C0402]  142.06 27.26 180 top
C206  -  [M-C0603]  151.46 105.87 270 bottom
C207  -  [M-C0402]  157.68 112.09 270 bottom
C208  -  [M-C0603]  131.14 121.9 0 bottom
C209  -  [M-C0402]  130.38 126.32 270 bottom
C210  -  [M-C0603]  171.09 136.3 0 top
C211  -  [M-C0603]  171.12 141.79 0 top
C212  -  [M-C0603]  131.39 105.74 270 bottom
C213  -  [M-C0603]  121.74 130.76 180 bottom
C214  -  [M-C0402]  165.81 25.48 0 bottom
C215  -  [M-C0603]  148.67 105.87 270 bottom
C216  -  [M-C0402]  183.84 151.72 90 top
C217  -  [M-C0603]  138.89 105.74 270 bottom
C218  -  [M-C0603]  141.43 105.74 270 bottom
C219  -  [M-C0402]  130.89 124.89 0 bottom
C220  -  [M-C0603]  121.74 129.37 180 bottom
C221  -  [M-C0603]  133.43 30.31 180 top
C222  -  [M-C0603]  121.87 26.37 0 bottom
C223  -  [M-C0402]  126.95 45.93 0 bottom
C224  -  [M-C0402]  126.95 43.26 0 bottom
C225  -  [M-C0402]  76.83 39.83 270 top
C226  -  [M-C0402]  148.54 40.59 270 top
C227  -  [M-C0402]  149.3 28.65 0 top
C228  -  [M-C0402]  135.38 38.97 0 top
C229  -  [M-C0402]  127.02 41.53 0 bottom
C230  -  [M-C0402]  147.65 40.59 270 top
C231  -  [M-C0402]  65.53 63.33 180 top
C232  -  [M-C0402]  36.01 37.68 90 top
C233  -  [M-C0402]  133.04 40.08 0 top
C234  -  [M-C0402]  127.05 40.64 0 bottom
C235  -  [M-C0402]  127.05 39.75 0 bottom
C236  -  [M-C0402]  133.04 40.97 0 top
C237  -  [M-C0402]  126.95 44.15 0 bottom
C239  -  [M-C0402]  126.95 45.04 0 bottom
C240  -  [M-C0402]  78.1 39.83 270 top
C241  -  [M-C0402]  120.47 37.54 0 bottom
C242  -  [M-C0402]  120.47 36.66 0 bottom
C243  -  [M-C0402]  135.36 40.01 0 top
C244  -  [M-C0402]  36.02 35.9 270 top
C245  -  [M-C0402]  133.04 38.81 0 top
C246  -  [M-C0402]  98.5 54.31 0 top
C247  -  [M-C0402]  100.79 50.32 270 top
C248  -  [M-C0402]  100.79 52.1 90 top
C249  -  [M-C0402]  133.04 37.93 0 top
C250  -  [M-C0402]  127.02 42.42 0 bottom
C252  -  [M-C0402]  89.99 52.53 180 top
C253  -  [M-C0402]  174.7 21.8 180 top
C254  -  [M-C0402]  178.92 24.18 270 top
C255  -  [M-C0402]  114.12 5.92 0 top
C256  -  [M-C0402]  79.35 39.83 270 top
C257  -  [M-C0402]  19.51 147.65 270 bottom
C258  -  [M-C0402]  80.62 39.83 270 top
C259  -  [M-C0402]  175.72 23.7 180 top
C260  -  [M-C0402]  110.06 10.24 270 top
C261  -  [M-C0402]  109.55 37.54 270 bottom
C262  -  [M-C0402]  114.5 40.34 270 top
C263  -  [M-C0402]  89.99 53.42 180 top
C264  -  [M-C0402]  95.33 56.09 90 top
C265  -  [M-C0402]  92.4 47.2 270 top
C266  -  [M-C0402]  93.29 47.2 270 top
C267  -  [M-C0402]  96.16 47.2 270 top
C268  -  [M-C0402]  110.44 37.54 270 bottom
C269  -  [M-C0402]  115.39 40.34 270 top
C270  -  [M-C0402]  113.11 40.34 270 bottom
C271  -  [M-C0402]  111.33 37.54 270 bottom
C272  -  [M-C0402]  24.33 116.79 180 top
C273  -  [M-C0402]  14.05 118.7 0 top
C274  -  [M-C0402]  23.19 150.07 180 bottom
C275  -  [M-C0402]  112.22 40.34 270 bottom
C276  -  [M-C0402]  104.85 30.94 90 bottom
C277  -  [M-C0402]  105.36 29.47 0 bottom
C278  -  [M-C0402]  23.32 137.49 0 bottom
C279  -  [M-C0402]  190.7 158.58 270 top
C280  -  [M-C0402]  134.06 15.07 180 top
C281  -  [M-C0402]  134.06 16.46 180 top
C282  -  [M-C0402]  20.14 150.07 180 bottom
C283  -  [M-C0603]  110.69 15.7 90 bottom
C284  -  [M-C0402]  131.77 11.38 90 top
C285  -  [M-C0402]  128.35 11.38 90 top
C286  -  [M-C0402]  190.85 97.89 90 top
C287  -  [M-C0402]  124.66 47.2 0 bottom
C288  -  [M-C0402]  182.7 141.81 0 top
C289  -  [M-C0402]  179.27 141.81 90 top
C290  -  [M-C0402]  95.83 25.23 0 top
C291  -  [M-C0402]  106.12 6.18 90 bottom
C292  -  [M-C0402]  169.11 8.59 90 top
C293  -  [M-C0402]  15.06 142.83 90 bottom
C294  -  [M-C0402]  156.03 8.72 0 top
C295  -  [M-C0402]  92.58 57.61 90 top
C296  -  [M-C0402]  168.22 8.59 90 top
C297  -  [M-C0402]  153.36 14.3 90 top
C298  -  [M-C0402]  154.63 14.3 90 top
C299  -  [M-C0402]  109.04 10.24 90 bottom
C300  -  [M-C0402]  124.66 48.09 0 bottom
C305  -  [M-C0402]  161.62 150.45 180 bottom
C308  -  [M-C0402]  193.8 95.33 0 top
C309  -  [M-C0402]  48.59 69.29 90 top
C310  -  [M-C0402]  193.83 93.42 0 top
C311  -  [M-C0402]  59.56 62.31 90 top
C320  -  [M-C0402]  132.66 11.38 90 top
C321  -  [M-C0402]  100.28 41.1 270 top
C322  -  [M-C0402]  132.66 36.4 90 top
C323  -  [M-C0402]  115.65 21.16 0 bottom
C324  -  [M-C0402]  130.5 11.89 0 top
C325  -  [M-C0402]  124.15 26.24 180 bottom
C326  -  [M-C0402]  109.17 16.72 90 bottom
C327  -  [M-C0402]  123.52 28.15 180 bottom
C328  -  [M-C0402]  110.44 20.91 270 bottom
C329  -  [M-C0402]  121.36 28.15 180 bottom
C330  -  [M-C0402]  89.99 64.47 90 top
C331  -  [M-C0402]  117.17 26.37 90 bottom
C332  -  [M-C0402]  97.23 47.2 270 top
C333  -  [M-C0402]  83.64 65.48 90 top
C334  -  [M-C0402]  145.52 52.45 0 bottom
C335  -  [M-C0402]  151.18 51.03 180 bottom
C339  -  [M-C0402]  129.23 11.38 90 top
C340  -  [M-C0603]  117.42 24.44 0 bottom
C341  -  [M-C0402]  113.11 16.72 0 bottom
C345  -  [M-C0402]  63.7 156.29 90 bottom
C346  -  [M-C0402]  64.59 156.29 90 bottom
C347  -  [M-C0402]  144.22 16.34 180 bottom
C349  -  [M-C0402]  61.04 156.29 270 bottom
C351  -  [M-C0402]  60.15 156.29 270 bottom
C352  -  [M-C0402]  62.81 156.29 270 bottom
C353  -  [M-C0402]  52.4 53.55 0 top
C354  -  [M-C0402]  61.92 156.29 270 bottom
C355  -  [M-C0402]  52.4 55.45 180 top
C359  -  [M-C0402]  98.6 52.4 0 top
C360  -  [M-C0402]  59.26 156.29 270 bottom
C361  -  [M-C0402]  58.37 156.29 270 bottom
C362  -  [M-C0402]  56.59 156.29 270 bottom
C363  -  [M-C0402]  57.48 156.29 270 bottom
C364  -  [M-C0402]  137.24 128.86 270 bottom
C365  -  [M-C0402]  63.51 167.97 90 top
C366  -  [M-C0402]  132.54 126.57 90 bottom
C367  -  [M-C0402]  137.24 126.57 90 bottom
C368  -  [M-C0402]  142.57 127.84 90 bottom
C369  -  [M-C0402]  67.07 167.97 90 top
C370  -  [M-C0402]  145.64 129.11 0 bottom
C371  -  [M-C0402]  130.38 114 90 bottom
C372  -  [M-C0402]  149.68 125.17 0 bottom
C373  -  [M-C0402]  150.44 91.77 90 top
C374  -  [M-C0402]  112.34 88.73 90 bottom
C375  -  [M-C0402]  148.72 127.77 180 bottom
C376  -  [M-C0402]  157.22 129.75 180 bottom
C377  -  [M-C0402]  155.4 125.3 270 bottom
C378  -  [M-C0402]  132.03 107.9 90 bottom
C379  -  [M-C0603]  87.58 56.85 90 top
C380  -  [M-C0402]  147.65 91.77 90 top
C381  -  [M-C0402]  143.84 110.32 180 bottom
C382  -  [M-C0402]  165.61 133.53 270 bottom
C383  -  [M-C0402]  166.5 133.53 270 bottom
C384  -  [M-C0402]  113.23 88.73 90 bottom
C385  -  [M-C0402]  116.03 80.98 270 bottom
C386  -  [M-C0402]  116.92 80.98 270 bottom
C387  -  [M-C0402]  171.91 76.41 90 bottom
C388  -  [M-C0402]  142.19 77.17 0 bottom
C389  -  [M-C0402]  113.49 75.9 180 bottom
C390  -  [M-C0402]  113.49 75.01 180 bottom
C391  -  [M-C0402]  116.66 67.9 270 bottom
C392  -  [M-C0402]  115.77 67.9 270 bottom
C393  -  [M-C0402]  65.84 161.37 0 top
C394  -  [M-C0402]  65.86 160.48 0 top
C395  -  [M-C0402]  144.47 124.92 270 bottom
C396  -  [M-C0402]  144.98 131.02 90 bottom
C397  -  [M-C0402]  130.89 128.6 270 bottom
C398  -  [M-C0402]  139.14 128.35 0 bottom
C399  -  [M-C0402]  150.44 132.16 180 bottom
C400  -  [M-C0402]  87.73 95.59 180 bottom
C401  -  [M-C0402]  150.57 141.07 180 bottom
C402  -  [M-C0603]  61.34 59.39 0 top
C403  -  [M-C0402]  66.18 167.97 90 top
C404  -  [M-C0402]  64.4 167.97 90 top
C405  -  [M-C0402]  87.71 94.57 180 bottom
C406  -  [M-C0402]  82.87 89.14 90 bottom
C407  -  [M-C0402]  44.02 62.06 270 bottom
C408  -  [M-C0402]  71.13 167.97 90 top
C409  -  [M-C0402]  72.02 167.97 90 top
C410  -  [M-C0402]  45.92 158.45 0 bottom
C411  -  [M-C0402]  68.59 167.97 90 top
C412  -  [M-C0402]  76.91 49.1 180 top
C413  -  [M-C0402]  79.83 46.56 90 top
C414  -  [M-C0402]  69.48 167.97 90 top
C415  -  [M-C0402]  81.98 89.14 90 bottom
C416  -  [M-C0402]  54.05 70.31 270 bottom
C417  -  [M-C0402]  41.73 134.45 0 top
C418  -  [M-C0402]  100.1 128.53 180 top
C419  -  [M-C0402]  53.03 157.43 90 top
C420  -  [M-C0402]  40.84 69.8 0 bottom
C421  -  [M-C0402]  80.09 93.04 180 bottom
C422  -  [M-C0402]  68.66 90.38 0 bottom
C423  -  [M-C0402]  61.92 142.07 90 bottom
C424  -  [M-C0402]  62.43 149.69 90 bottom
C425  -  [M-C0402]  69.42 75.14 270 bottom
C426  -  [M-C0402]  41.86 162.92 180 bottom
C427  -  [M-C0402]  82.12 133.18 270 top
C428  -  [M-C0402]  60.27 163.4 180 top
C429  -  [M-C0402]  97.61 140.03 270 top
C430  -  [M-C0402]  97.36 142.57 90 top
C431  -  [M-C0402]  61.16 169.5 0 top
C432  -  [M-C0402]  56.97 158.7 0 top
C433  -  [M-C0402]  97.36 144.35 90 top
C435  -  [M-C0402]  57.1 169.37 180 top
C436  -  [M-C0402]  181.56 159.08 90 top
C438  -  [M-C0402]  179.4 145.49 90 top
C445  -  [M-C0402]  28.02 162.89 90 top
C450  -  [M-C0402]  114.88 165.56 180 bottom
C452  -  [M-C0402]  74.24 161.88 0 top
C456  -  [M-C0402]  20.14 46.18 0 top
C465  -  [M-C0402]  67.89 156.8 180 bottom
C466  -  [M-C0402]  65.99 156.8 180 bottom
C469  -  [M-C0402]  40.84 167.59 90 top
C470  -  [M-C0402]  41.73 167.59 90 top
C473  -  [M-C0402]  77.16 163.02 270 top
C486  -  [M-C0402]  183.72 80.98 180 bottom
C492  -  [M-C0402]  150.44 9.22 270 top
C493  -  [M-C0402]  151.59 9.22 270 top
C498  -  [M-C0402]  108.66 37.54 270 bottom
C499  -  [M-C0402]  126.82 173.56 0 top
C500  -  [M-C0402]  129.36 173.05 0 bottom
C522  -  [M-C0402]  83.26 73.23 180 top
C529  -  [M-C0402]  89.2 160.35 270 top
C540  -  [M-C0402]  13.59 82.93 180 top
C544  -  [M-C0402]  16.33 72.72 0 bottom
C545  -  [M-C0402]  59.51 162.51 180 top
C546  -  [M-C0402]  11.56 74.37 270 top
C548  -  [M-C0402]  12.14 70.56 90 bottom
C550  -  [M-C0402]  22.68 106.89 270 top
C553  -  [M-C0603]  181.08 78.44 90 bottom
C554  -  [M-C0402]  10.74 83.21 180 top
C556  -  [M-C0402]  4.77 106.51 180 top
C559  -  [M-C0402]  2.36 106 0 top
C576  -  [M-C0805]  124.28 170.89 270 bottom
C577  -  [M-C0603]  146.63 131.4 0 bottom
C578  -  [M-C0603]  41.48 169.37 0 top
C579  -  [M-C0603]  136.47 114.38 0 bottom
C580  -  [M-C0603]  126.31 140.92 270 top
C581  -  [M-C0402]  182.22 104.27 90 top
C582  -  [M-C0603]  128.55 138.97 180 top
C583  -  [M-C0603]  127.71 140.92 270 top
C584  -  [M-C0603]  125.68 145.24 90 bottom
C585  -  [M-C0603]  150.32 133.3 180 bottom
C586  -  [M-C0603]  164.54 126.57 0 bottom
C587  -  [M-C0603]  140.03 145.24 90 bottom
C588  -  [M-C0402]  188.29 152.1 180 top
C589  -  [M-C0603]  137.24 145.24 90 bottom
C590  -  [M-C0603]  134.57 124.79 180 bottom
C591  -  [M-C0603]  144.22 145.24 90 bottom
C592  -  [M-C0402]  181.81 153.11 0 top
C593  -  [M-C0603]  128.85 145.24 90 bottom
C594  -  [M-C0603]  127.46 145.24 90 bottom
C595  -  [M-C0402]  43.51 167.59 270 top
C596  -  [M-C0603]  44.78 167.47 90 top
C597  -  [M-C0603]  41.48 170.77 0 top
C598  -  [M-C0603]  164.54 130.89 0 bottom
C599  -  [M-C0603]  171.12 140.41 0 top
C600  -  [M-C0603]  171.12 139.04 0 top
C601  -  [M-C0603]  162.89 141.81 90 bottom
C602  -  [M-C0402]  189.56 149.81 270 top
C603  -  [M-C0603]  121.49 145.24 90 bottom
C604  -  [M-C0603]  122.88 145.24 90 bottom
C605  -  [M-C0603]  120.09 145.24 90 bottom
C606  -  [M-C0603]  164.54 128.1 0 bottom
C607  -  [M-C0603]  134.44 145.24 90 bottom
C608  -  [M-C0603]  135.84 145.24 90 bottom
C609  -  [M-C0603]  142.82 145.24 90 bottom
C610  -  [M-C0402]  61.29 176.36 0 top
C611  -  [M-C0603]  147.01 145.24 90 bottom
C612  -  [M-C0603]  118.82 145.24 90 bottom
C613  -  [M-C0603]  148.41 145.24 90 bottom
C614  -  [M-C0603]  141.43 145.24 90 bottom
C615  -  [M-C0402]  182.32 151.72 270 top
C616  -  [M-C0603]  138.63 145.24 90 bottom
C617  -  [M-C0603]  130.25 145.24 90 bottom
C618  -  [M-C0603]  145.62 145.24 90 bottom
C619  -  [M-C0603]  131.65 145.24 90 bottom
C620  -  [M-C0603]  133.04 145.24 90 bottom
C621  -  [M-C0603]  162.64 132.29 0 bottom
C622  -  [M-C0603]  164.54 129.49 0 bottom
C623  -  [M-C0603]  162.64 133.68 0 bottom
C624  -  [M-C0603]  124.28 145.24 90 bottom
C625  -  [M-C0603]  168.48 141.84 90 bottom
C626  -  [M-C0603]  164.29 141.81 90 bottom
C627  -  [M-C0603]  167.08 141.81 90 bottom
C628  -  [M-C0603]  165.68 141.81 90 bottom
C629  -  [M-C1808]  78.17 174.59 180 top
C630  -  [M-C0805]  126.31 170.89 270 bottom
C631  -  [M-C0805]  121.87 172.8 180 top
C632  -  [M-C0805]  125.81 172.16 0 top
C641  -  [M-C0402]  184.48 162.89 90 top
C653  -  [M-C0402]  186.26 162.89 90 top
C654  -  [M-C0402]  192.61 144.35 0 top
C656  -  [M-C0402]  190.07 144.35 0 top
C663  -  [M-C0402]  9.09 98.76 270 top
C665  -  [M-C0402]  10.62 99.9 180 top
C666  -  [M-C0402]  6.96 106.63 180 top
C667  -  [M-C0402]  78.94 157.31 270 bottom
C668  -  [M-C0402]  8.46 106.89 90 top
C669  -  [M-C0402]  79.07 157.43 270 top
C673  -  [M-C0402]  4.77 104.22 270 top
C674  -  [M-C7343]  26.11 86.11 270 top
C675  -  [M-C7343]  145.74 141.05 0 top
C677  -  [M-C0603]  92.33 88.06 270 bottom
C686  -  [M-C0603]  22.94 89.74 180 bottom
C687  -  [M-C0603]  51.13 81.11 90 bottom
C688  -  [M-C0603]  68.27 88.6 45 bottom
C689  -  [M-C0603]  22.94 88.34 180 bottom
C690  -  [M-C0603]  22.94 79.45 180 bottom
C692  -  [M-C0603]  41.86 141.05 0 bottom
C693  -  [M-C0603]  41.86 143.08 0 top
C694  -  [M-C0603]  41.86 146.64 0 top
C695  -  [M-C0603]  41.86 144.99 0 top
C696  -  [M-C0603]  41.86 141.43 0 top
C697  -  [M-C0603]  41.86 133.56 0 bottom
C698  -  [M-C0603]  41.86 139.4 0 bottom
C699  -  [M-C0603]  41.86 149.18 0 bottom
C700  -  [M-C0603]  41.86 145.49 0 bottom
C701  -  [M-C0603]  41.86 148.16 0 top
C702  -  [M-C0603]  41.86 135.59 0 top
C703  -  [M-C0603]  41.86 137.75 0 top
C719  -  [M-C0603]  93.72 88.06 270 bottom
C720  -  [M-C0402]  21.41 74.25 270 bottom
C738  -  [M-C0402]  173.81 162.77 270 top
C782  -  [M-C0402]  87.81 103.19 0 bottom
C783  -  [M-C0402]  90.11 102.87 180 bottom
C784  -  [M-C0402]  87.81 104.07 0 bottom
C785  -  [M-C0402]  89.75 104.81 180 bottom
C788  -  [M-C0402]  108.03 115.52 180 bottom
C789  -  [M-C0402]  108.03 110.95 180 bottom
C796  -  [M-C0402]  22.1 65.89 0 bottom
C797  -  [M-C0402]  13.92 110.82 0 top
C798  -  [M-C0402]  24.64 66.73 270 bottom
C799  -  [M-C0402]  16.08 112.22 270 top
C800  -  [M-C0402]  14.3 114.63 180 top
C801  -  [M-C0402]  14.17 72.6 180 top
C802  -  [M-C0402]  15.57 72.22 90 top
C803  -  [M-C0402]  18.01 111.08 90 top
C804  -  [M-C0402]  25.35 131.14 0 top
C805  -  [M-C0402]  23.32 132.03 0 top
C806  -  [M-C0402]  25.35 146.51 0 top
C807  -  [M-C0402]  23.44 147.4 0 top
C808  -  [M-C0402]  25.22 158.58 0 top
C809  -  [M-C0402]  25.22 159.46 180 top
C816  -  [M-C0603]  17.47 66.25 180 bottom
C817  -  [M-C0603]  18.62 74.5 90 bottom
C818  -  [M-C0402]  24.15 70.92 0 bottom
C819  -  [M-C0402]  68.78 92.41 180 bottom
C821  -  [M-C0402]  105.99 114.38 180 bottom
C822  -  [M-C0402]  108.03 116.41 180 bottom
C823  -  [M-C0402]  108.03 113.24 180 bottom
C824  -  [M-C0402]  105.99 115.27 180 bottom
C825  -  [M-C0402]  105.99 112.09 180 bottom
C826  -  [M-C0402]  108.03 114.13 180 bottom
C827  -  [M-C0402]  105.99 109.81 180 bottom
C828  -  [M-C0402]  105.99 112.98 180 bottom
C829  -  [M-C0402]  108.03 111.84 180 bottom
C830  -  [M-C0402]  108.03 108.66 180 bottom
C831  -  [M-C0402]  105.99 110.7 180 bottom
C832  -  [M-C0402]  105.99 107.52 180 bottom
C833  -  [M-C0402]  108.03 109.55 180 bottom
C834  -  [M-C0402]  105.99 108.41 180 bottom
C846  -  [M-C0402]  105.99 105.11 180 bottom
C847  -  [M-C0402]  107.9 107.27 180 bottom
C848  -  [M-C0402]  107.9 106.38 180 bottom
C849  -  [M-C0402]  82.78 108.54 0 bottom
C851  -  [M-C0402]  105.99 106 180 bottom
C852  -  [M-C0402]  105.99 102.82 180 bottom
C853  -  [M-C0402]  108.03 104.85 180 bottom
C854  -  [M-C0402]  108.03 103.97 180 bottom
C855  -  [M-C0402]  105.99 103.71 180 bottom
C856  -  [M-C0603]  97.36 92.92 0 bottom
C857  -  [M-C0402]  85.07 88.7 180 bottom
C858  -  [M-C0402]  83.76 89.14 270 bottom
C859  -  [M-C0402]  105.99 100.54 180 bottom
C860  -  [M-C0603]  97.27 94.3 0 bottom
C861  -  [M-C0603]  84.61 86.16 270 bottom
C862  -  [M-C0603]  82.5 86.01 270 bottom
C863  -  [M-C0402]  87.83 98.5 0 bottom
C864  -  [M-C0402]  87.83 100.66 0 bottom
C865  -  [M-C0603]  81.61 65.87 0 top
C866  -  [M-C0603]  97.22 95.59 0 bottom
C867  -  [M-C0402]  108.03 102.57 180 bottom
C868  -  [M-C0402]  107.99 101.69 180 bottom
C870  -  [M-C0402]  87.83 101.81 0 bottom
C871  -  [M-C0603]  78.56 77.04 180 top
C872  -  [M-C0402]  108.15 63.71 90 top
C874  -  [M-C0402]  81.1 140.16 270 top
C875  -  [M-C0402]  79.2 137.87 0 bottom
C876  -  [M-C0402]  81.48 138.13 180 bottom
C877  -  [M-C0402]  38.94 122.13 90 bottom
C878  -  [M-C0402]  46.3 138 180 bottom
C879  -  [M-C0402]  39.11 87.18 90 bottom
C880  -  [M-C0402]  81.99 140.16 270 top
C881  -  [M-C0402]  72.72 89.13 270 bottom
C882  -  [M-C0402]  68.82 106.64 180 bottom
C883  -  [M-C0402]  68.78 99.65 180 bottom
C884  -  [M-C0402]  35.51 121.36 0 top
C885  -  [M-C0402]  69.04 133.68 270 bottom
C886  -  [M-C0402]  72.34 133.68 270 bottom
C887  -  [M-C0402]  63.19 142.57 90 top
C888  -  [M-C0402]  63.19 140.8 270 top
C889  -  [M-C0603]  74.24 148.29 0 top
C890  -  [M-C0402]  77.16 132.67 90 bottom
C891  -  [M-C0603]  68.53 148.16 0 top
C892  -  [M-C0603]  65.1 148.16 0 top
C893  -  [M-C0402]  63.58 133.56 270 bottom
C894  -  [M-C0603]  68.15 146.89 180 bottom
C895  -  [M-C0402]  63.83 138 90 bottom
C896  -  [M-C0603]  65.86 147.65 270 bottom
C897  -  [M-C0603]  75.01 148.54 0 bottom
C898  -  [M-C0402]  82.75 132.92 270 bottom
C899  -  [M-C0603]  84.66 148.29 180 bottom
C900  -  [M-C0603]  89.23 148.29 180 top
C901  -  [M-C0402]  91.9 134.83 0 bottom
C902  -  [M-C0603]  89.23 148.29 0 bottom
C903  -  [M-C0603]  94.31 148.29 0 top
C904  -  [M-C0402]  96.34 136.22 90 bottom
C905  -  [M-C0402]  82.63 140.92 90 bottom
C906  -  [M-C0402]  82.63 143.08 270 bottom
C907  -  [M-C0402]  82.63 146 90 bottom
C908  -  [M-C0402]  96.6 140.29 180 bottom
C909  -  [M-C0603]  95.45 147.91 0 bottom
C910  -  [M-C0603]  81.86 144.35 90 top
C911  -  [M-C0402]  43.26 112.35 0 bottom
C912  -  [M-C0402]  43.89 106.76 180 bottom
C913  -  [M-C0402]  40.72 106.76 0 bottom
C914  -  [M-C0402]  33.98 106.76 0 bottom
C915  -  [M-C0402]  31.83 106.76 0 bottom
C916  -  [M-C0603]  29.41 108.54 270 bottom
C917  -  [M-C0402]  39.95 115.4 180 bottom
C918  -  [M-C0402]  43.51 115.4 180 bottom
C919  -  [M-C0402]  34.11 106.25 180 top
C920  -  [M-C0402]  36.14 106.25 0 top
C921  -  [M-C0402]  44.27 121.36 0 top
C922  -  [M-C0603]  29.29 117.3 90 bottom
C923  -  [M-C0603]  32.33 120.86 180 bottom
C924  -  [M-C0402]  62.28 143.39 90 top
C925  -  [M-C0402]  62.28 141.63 90 top
C926  -  [M-C0402]  47.07 132.79 270 top
C927  -  [M-C0402]  47.07 134.7 270 top
C928  -  [M-C0402]  46.94 142.95 270 top
C929  -  [M-C0603]  63.58 145.75 270 bottom
C930  -  [M-C0603]  57.61 146.89 0 bottom
C931  -  [M-C0402]  48.21 134.83 90 bottom
C932  -  [M-C0402]  48.21 132.92 90 bottom
C933  -  [M-C0402]  61.04 137.24 90 bottom
C934  -  [M-C0402]  57.23 140.16 90 bottom
C935  -  [M-C0402]  55.57 144.86 90 bottom
C936  -  [M-C0603]  49.86 147.02 0 bottom
C937  -  [M-C0603]  53.16 147.02 180 bottom
C938  -  [M-C0603]  65.86 125.3 90 bottom
C939  -  [M-C0402]  63.7 143.34 90 bottom
C940  -  [M-C0402]  72.21 136.86 270 bottom
C941  -  [M-C0402]  76.91 145.62 90 bottom
C942  -  [M-C0402]  71.7 140.54 180 bottom
C943  -  [M-C0603]  67.26 125.3 90 bottom
C944  -  [M-C0603]  68.66 125.3 90 bottom
C945  -  [M-C0603]  81.48 144.35 90 bottom
C946  -  [M-C0603]  28.9 117.3 90 top
C947  -  [M-C0402]  87.32 138.89 270 bottom
C948  -  [M-C0603]  96.98 142.83 90 bottom
C949  -  [M-C0402]  91.39 136.86 270 bottom
C950  -  [M-C0402]  91.64 140.54 0 bottom
C951  -  [M-C0603]  96.98 145.75 90 bottom
C952  -  [M-C0402]  33.35 121.49 0 top
C953  -  [M-C0603]  28.9 111.84 90 top
C954  -  [M-C0603]  92.91 148.29 180 bottom
C955  -  [M-C0402]  47.07 139.4 270 top
C956  -  [M-C0402]  88.72 141.68 90 bottom
C957  -  [M-C0402]  90.5 144.73 270 bottom
C958  -  [M-C0603]  28.9 108.54 270 top
C959  -  [M-C0603]  51.38 114.51 0 bottom
C960  -  [M-C0603]  52.65 105.24 180 bottom
C961  -  [M-C0603]  50.88 116.54 0 bottom
C962  -  [M-C0603]  61.04 133.43 90 bottom
C963  -  [M-C0402]  61.92 145.62 270 bottom
C964  -  [M-C0603]  52.78 148.16 180 top
C965  -  [M-C0603]  49.48 148.16 0 top
C966  -  [M-C0603]  46.81 145.11 90 top
C967  -  [M-C0603]  57.61 148.16 0 top
C968  -  [M-C0603]  60.15 148.16 180 top
C969  -  [M-C0603]  87.48 110.65 90 bottom
C970  -  [M-C0603]  82.62 102.17 270 bottom
C971  -  [M-C0603]  91.52 113.62 0 bottom
C972  -  [M-C0402]  68.27 140.16 90 bottom
C973  -  [M-C0402]  38.05 86.57 180 top
C974  -  [M-C0603]  45.92 82.12 90 bottom
C975  -  [M-C0603]  28.9 73.99 270 top
C976  -  [M-C0402]  34.37 71.2 180 top
C977  -  [M-C0402]  33.35 84.66 270 bottom
C978  -  [M-C0402]  43.38 80.47 180 bottom
C979  -  [M-C0402]  44.53 84.92 180 bottom
C980  -  [M-C0402]  43.26 72.34 0 bottom
C981  -  [M-C0402]  69.16 140.16 90 bottom
C982  -  [M-C0402]  69.8 144.86 270 bottom
C983  -  [M-C0603]  77.8 141.18 270 bottom
C984  -  [M-C0402]  63.07 145.49 90 top
C985  -  [M-C0402]  77.16 134.45 90 bottom
C986  -  [M-C0402]  96.6 138.38 90 bottom
C987  -  [M-C0402]  88.09 136.99 90 bottom
C988  -  [M-C0603]  84.66 148.29 180 top
C989  -  [M-C0402]  88.09 133.56 90 bottom
C990  -  [M-C0402]  82.75 134.7 90 bottom
C991  -  [M-C0402]  34.62 120.73 0 bottom
C992  -  [M-C0402]  44.27 120.73 180 bottom
C993  -  [M-C0603]  46.56 109.68 180 bottom
C994  -  [M-C0402]  29.79 115.4 180 bottom
C995  -  [M-C0402]  42.37 121.36 180 top
C996  -  [M-C0402]  57.1 132.16 90 bottom
C997  -  [M-C0402]  42.75 84.92 180 bottom
C998  -  [M-C0603]  60.15 146.89 180 bottom
C999  -  [M-C0402]  53.03 133.56 90 bottom
C1000  -  [M-C0402]  52.65 140.54 180 bottom
C1001  -  [M-C0603]  29.41 111.71 90 bottom
C1002  -  [M-C0402]  42.37 120.73 180 bottom
C1003  -  [M-C0603]  47.7 145.11 270 bottom
C1004  -  [M-C0402]  47.83 140.92 90 bottom
C1005  -  [M-C0402]  78.31 143.84 270 top
C1006  -  [M-C0402]  78.31 141.94 90 top
C1007  -  [M-C0402]  69.04 136.99 90 bottom
C1008  -  [M-C0402]  74.04 88.73 180 bottom
C1009  -  [M-C0402]  82.12 134.95 270 top
C1010  -  [M-C0402]  82.12 142.19 90 top
C1011  -  [M-C0402]  40.08 112.22 180 bottom
C1012  -  [M-C0402]  36.8 111.59 180 bottom
C1013  -  [M-C0402]  31.95 112.98 180 bottom
C1014  -  [M-C0402]  56.46 136.86 90 bottom
C1015  -  [M-C0402]  53.03 136.86 270 bottom
C1016  -  [M-C0402]  55.7 142.45 270 bottom
C1017  -  [M-C0402]  36.14 86.57 180 top
C1018  -  [M-C0603]  29.28 76.8 270 bottom
C1019  -  [M-C0402]  36.27 71.2 180 top
C1020  -  [M-C0402]  34.24 71.86 90 bottom
C1021  -  [M-C0402]  36.02 79.84 270 bottom
C1022  -  [M-C0402]  40.21 77.17 180 bottom
C1023  -  [M-C0603]  29.28 73.87 270 bottom
C1024  -  [M-C0402]  40.33 80.34 0 bottom
C1025  -  [M-C0402]  41.22 72.34 0 bottom
C1026  -  [M-C0402]  31.19 77.55 90 bottom
C1027  -  [M-C0603]  29.03 81.99 90 bottom
C1028  -  [M-C0402]  32.08 86.36 180 top
C1029  -  [M-C0603]  29.03 81.99 90 top
C1030  -  [M-C0603]  51.13 84.41 270 bottom
C1031  -  [M-C0402]  43.26 77.3 0 bottom
C1032  -  [M-C0402]  36.91 76.41 0 bottom
C1033  -  [M-C0603]  31.7 70.82 180 top
C1034  -  [M-C0603]  28.9 79.33 270 top
C1035  -  [M-C0402]  47.32 74.12 0 top
C1036  -  [M-C0603]  30.99 71.76 90 bottom
C1037  -  [M-C0402]  42.75 86.44 0 top
C1038  -  [M-C0402]  44.65 86.44 0 top
C1039  -  [M-C0603]  28.9 76.79 270 top
C1040  -  [M-C0402]  38.43 90.12 180 top
C1041  -  [M-C0402]  31.32 105.36 180 top
C1042  -  [M-C0402]  39.06 89.49 270 bottom
C1043  -  [M-C0402]  12.93 73.92 180 top
C1044  -  [M-C0402]  41.73 115.4 0 bottom
C1045  -  [M-C0603]  41.35 104.6 0 bottom
C1046  -  [M-C0402]  36.14 105.36 0 top
C1047  -  [M-C0603]  46.94 91.01 180 bottom
C1048  -  [M-C0603]  28.9 92.79 270 top
C1049  -  [M-C0603]  44.65 104.6 0 bottom
C1050  -  [M-C0402]  40.59 96.47 90 bottom
C1051  -  [M-C0603]  28.9 95.96 270 top
C1052  -  [M-C0603]  46.05 108.03 180 bottom
C1053  -  [M-C0402]  29.79 104.35 180 bottom
C1054  -  [M-C0402]  44.78 90.88 180 bottom
C1055  -  [M-C0402]  43 90.88 0 bottom
C1056  -  [M-C0402]  35.13 90.76 0 bottom
C1057  -  [M-C0402]  33.35 90.76 180 bottom
C1058  -  [M-C0603]  29.54 90.38 0 bottom
C1059  -  [M-C0402]  42.62 95.96 180 bottom
C1060  -  [M-C0402]  39.32 99.52 0 bottom
C1061  -  [M-C0402]  39.19 95.71 270 bottom
C1062  -  [M-C0603]  31.57 90 270 bottom
C1063  -  [M-C0402]  32.21 98.63 180 bottom
C1064  -  [M-C0402]  33.22 105.36 0 top
C1065  -  [M-C0402]  75.77 131.4 180 bottom
C1066  -  [M-C0402]  92.02 132.16 90 bottom
C1067  -  [M-C0402]  37.16 80.72 270 bottom
C1068  -  [M-C0402]  44.27 90.12 180 top
